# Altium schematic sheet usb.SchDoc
size A3
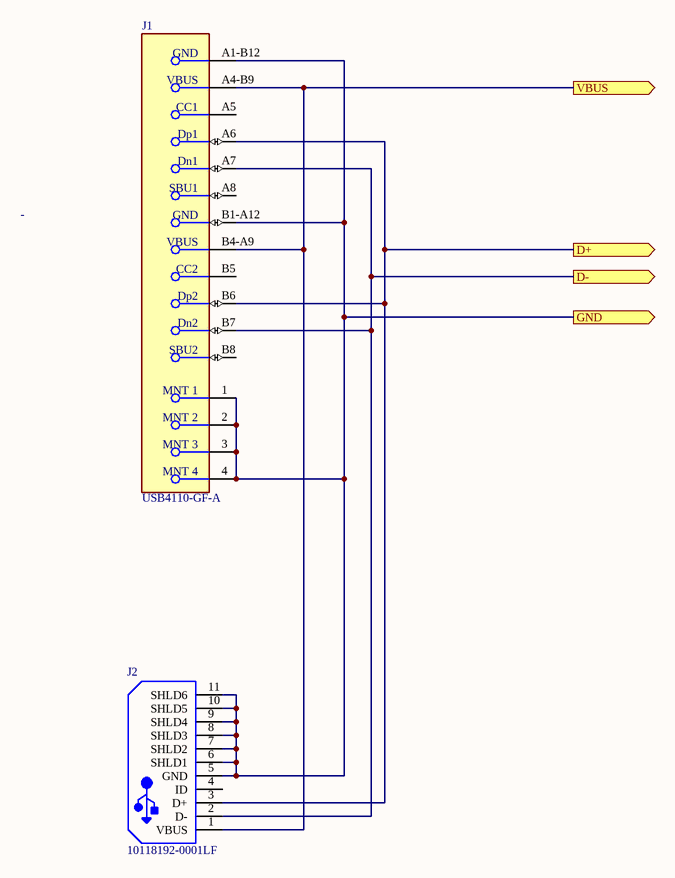
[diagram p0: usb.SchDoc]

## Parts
J1  USB4110-GF-A  [FP-USB4110-GF-A-MFG]
J2  10118192-0001LF  [FCI-10118192-0001LF-5_V]

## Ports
D+ (out), D- (out), GND (out), VBUS (out)

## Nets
D+: J1.A6(Dp1) J1.B6(Dp2) J2.3(D+) ; port D+
D-: J1.A7(Dn1) J1.B7(Dn2) J2.2(D-) ; port D-
GND: J1.1(MNT_1) J1.2(MNT_2) J1.3(MNT_3) J1.4(MNT_4) J1.A1-B12(GND) J1.B1-A12(GND) J2.5(GND) J2.6(SHLD1) J2.7(SHLD2) J2.8(SHLD3) J2.9(SHLD4) J2.10(SHLD5) J2.11(SHLD6) ; port GND
VBUS: J1.A4-B9(VBUS) J1.B4-A9(VBUS) J2.1(VBUS) ; port VBUS

Not connected (* = marked no-connect by the designer): J1 A5(CC1) A8(SBU1) B5(CC2) B8(SBU2); J2 4(ID)

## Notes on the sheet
- -

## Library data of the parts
J1 = CMP-ROOT-00018-1: Conn Usb 2.0 Type-c R/a SMT; Number of Positions: 12; System: Connector
J2 = CMP-ROOT-00010-2: CONN RCPT USB2.0 MICRO B SMD R/A; Voltage Rating: 100V; Number of Contacts: 5; Gender: Receptacle; System: Connector; Connector Type: USB,Receptacle; Current Rating: 1.8A; Number of Ports: 1; Insulation Resistance: 1GR; Pitch: 0.65mm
